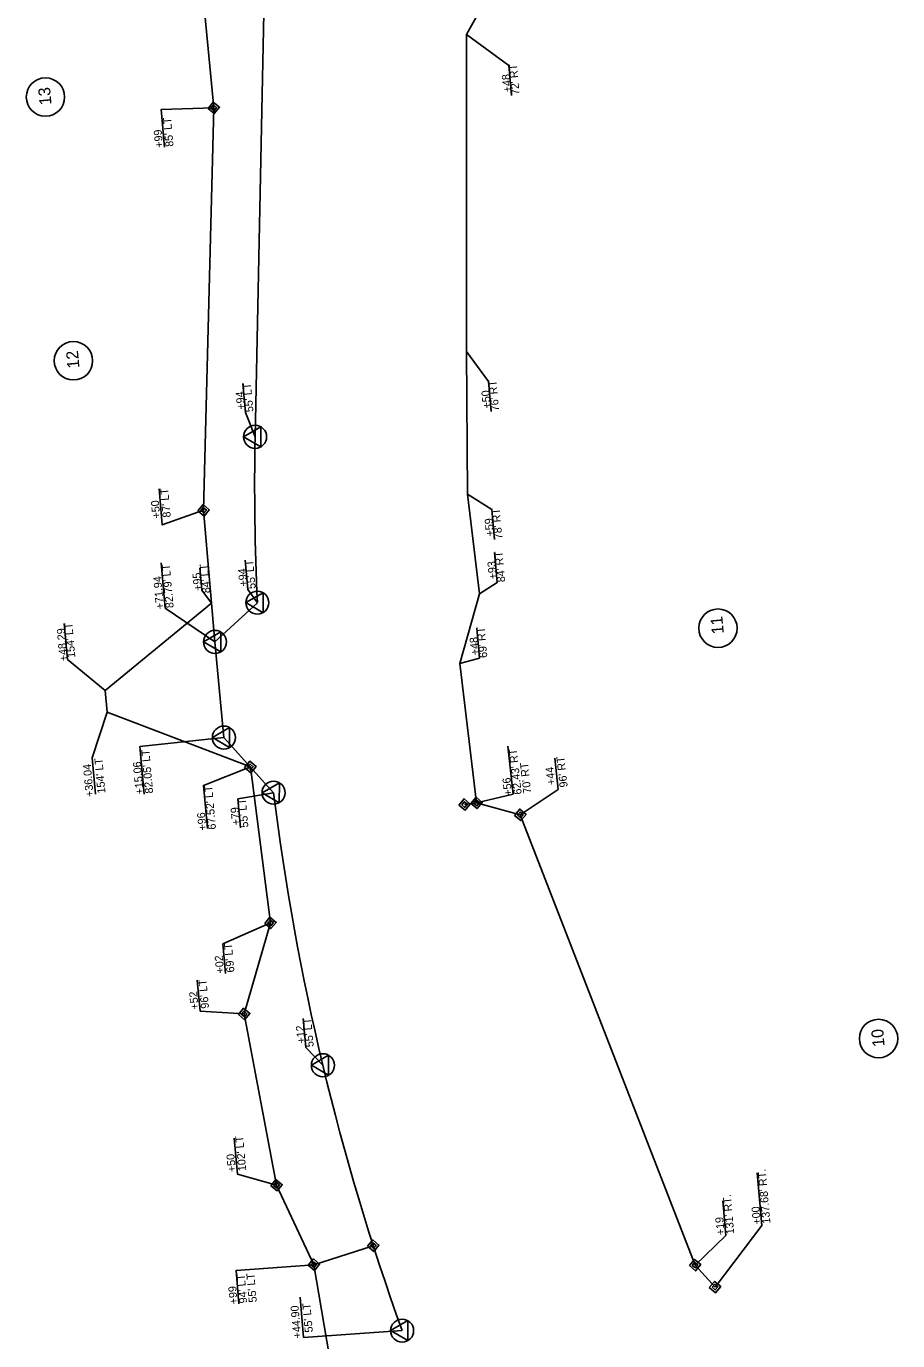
# Model space of a CAD drawing. Extents: x 1555582 to 1558054, y 687961 to 694065.
# Drawn here: x 1555953 to 1556498, y 690891 to 691713 of the extents above; entities that cross this region are included whole.
import ezdxf

# ---------------------------------------------------------------- set-up
doc = ezdxf.new("R2010")
doc.units = 0
for name, color, linetype in [('Exist Horizontal Alignment', 7, 'Continuous'), ('Exist Hydrographic FEMA Cross Section', 7, 'Continuous'), ('Exist Structure Major Bridge Seam', 7, 'Continuous'), ('Exist Structure Minor Drop Inlet Text', 7, 'Continuous'), ('Prop Approach Slab', 7, 'Continuous'), ('Prop Approach Slab Hatching', 7, 'Continuous'), ('Prop Boundary Easement Temporary Drainage Label', 7, 'Continuous'), ('Prop Drainage Structure Box Reinforced Concrete', 7, 'Continuous'), ('Prop Drainage Structure Catch Basin Grate 840 03F Label', 7, 'Continuous'), ('Prop Drainage Structure Catch Basin Grate 840 03G CELL', 7, 'Continuous'), ('Prop Drainage Structure Plot Symbol 50 Scale', 7, 'Continuous'), ('Prop Erosion Rip Rap Class II', 7, 'Continuous'), ('Prop Plan Preparation Excavation Hatching', 7, 'Continuous'), ('Scratch_Level_3', 7, 'Continuous')]:
    doc.layers.add(name, color=color, linetype=linetype)

msp = doc.modelspace()

# ---------------------------------------------------------------- linework, layer by layer
at = {"layer": 'Exist Horizontal Alignment'}
for p, q in [((1556088.15, 691489.59), (1556089.78, 691471.44)), ((1556089.56, 691379.07), (1556091.2, 691360.91)), ((1556023.7, 691262.72), (1556076.27, 691268.29)), ((1556023.7, 691262.72), (1556026.38, 691232.84)), ((1556084.98, 691229.93), (1556086.62, 691211.78)), ((1556125.85, 691092.78), (1556127.49, 691074.62)), ((1556123.88, 690918.49), (1556126.14, 690893.4)), ((1556126.14, 690893.4), (1556187.74, 690897.67))]:
    msp.add_line(p, q, dxfattribs=at)
for points in [[(1556089.78, 691471.44), (1556095.82, 691456.22)], [(1556036.97, 691377.54), (1556039.52, 691349.16), (1556070.71, 691328.04)], [(1556091.2, 691360.91), (1556097.21, 691352.58)], [(1556084.98, 691229.93), (1556107.34, 691233.83)], [(1556127.49, 691074.62), (1556138.16, 691063.56)]]:
    msp.add_lwpolyline(points, dxfattribs=at)
at = {"layer": 'Exist Hydrographic FEMA Cross Section'}
for p, q in [((1556095.82, 691456.22), (1556102.69, 691797.16)), ((1556070.71, 691328.04), (1556097.21, 691352.58)), ((1556076.27, 691268.29), (1556070.71, 691328.04)), ((1556107.34, 691233.83), (1556076.27, 691268.29))]:
    msp.add_line(p, q, dxfattribs=at)
for centre, radius, start, end in [((1557645.4, 691425.17), 1549.89, 178.85195, 182.68426), ((1557650.51, 691425.24), 1555, 187.07064, 199.83242)]:
    msp.add_arc(centre, radius, start, end, dxfattribs=at)
at = {"layer": 'Exist Structure Major Bridge Seam'}
for p, q in [((1556253.81, 691262.83), (1556257.14, 691233.01)), ((1556283.16, 691255.33), (1556285.35, 691235.76)), ((1556409.75, 690996.29), (1556412.71, 690963.43)), ((1556388.17, 690978.79), (1556390.13, 690957.04))]:
    msp.add_line(p, q, dxfattribs=at)
for points in [[(1556257.14, 691233.01), (1556234.25, 691227.48)], [(1556285.35, 691235.76), (1556261.6, 691219.95)], [(1556412.71, 690963.43), (1556383.4, 690924.9)], [(1556390.13, 690957.04), (1556370.92, 690938.61)]]:
    msp.add_lwpolyline(points, dxfattribs=at)
at = {"layer": 'Exist Structure Minor Drop Inlet Text'}
for p, q in [((1556254.53, 691688.34), (1556256.21, 691669.6)), ((1556241.73, 691490.73), (1556243.42, 691471.99)), ((1556243.77, 691410.76), (1556245.45, 691392.02)), ((1556245.53, 691383.89), (1556247.21, 691365.14)), ((1556061.33, 691374.32), (1556062.58, 691360.37)), ((1555976.47, 691339.66), (1555978.51, 691317)), ((1556234.37, 691336.57), (1556236.06, 691317.83)), ((1555978.51, 691317), (1556002.02, 691297.7)), ((1555993.99, 691255.63), (1555996.04, 691232.87))]:
    msp.add_line(p, q, dxfattribs=at)
for points in [[(1556254.53, 691688.34), (1556227.91, 691707.62)], [(1556241.73, 691490.73), (1556227.92, 691509.58)], [(1556243.77, 691410.76), (1556228.52, 691420.39)], [(1556247.21, 691365.14), (1556236.1, 691358.13)], [(1556062.58, 691360.37), (1556068.61, 691352.3)], [(1556236.06, 691317.83), (1556223.8, 691314.58)], [(1555993.99, 691255.63), (1556003.23, 691284.25)]]:
    msp.add_lwpolyline(points, dxfattribs=at)
at = {"layer": 'Prop Approach Slab'}
for p, q in [((1556069.96, 691661.8), (1556057.79, 691787.39)), ((1556063.58, 691410.31), (1556069.96, 691661.8)), ((1556070.71, 691328.04), (1556063.58, 691410.31)), ((1556105.41, 691152.46), (1556092.82, 691249.93)), ((1556088.94, 691095.54), (1556105.41, 691152.46)), ((1556109.18, 690988.56), (1556088.94, 691095.54)), ((1556132.53, 690938.86), (1556109.18, 690988.56)), ((1556169.67, 690950.76), (1556132.53, 690938.86))]:
    msp.add_line(p, q, dxfattribs=at)
at = {"layer": 'Prop Approach Slab Hatching'}
for p, q in [((1556069.96, 691661.8), (1556069.96, 691661.8)), ((1556063.58, 691410.31), (1556063.58, 691410.31)), ((1556092.82, 691249.93), (1556092.82, 691249.93)), ((1556226.75, 691226.43), (1556226.75, 691226.43)), ((1556234.25, 691227.48), (1556234.25, 691227.48)), ((1556261.6, 691219.95), (1556261.6, 691219.95)), ((1556105.41, 691152.46), (1556105.41, 691152.46)), ((1556088.94, 691095.54), (1556088.94, 691095.54)), ((1556109.18, 690988.56), (1556109.18, 690988.56)), ((1556169.67, 690950.76), (1556169.67, 690950.76)), ((1556132.53, 690938.86), (1556132.53, 690938.86)), ((1556370.92, 690938.61), (1556370.92, 690938.61)), ((1556383.4, 690924.9), (1556383.4, 690924.9))]:
    msp.add_line(p, q, dxfattribs=at)
at = {"layer": 'Prop Boundary Easement Temporary Drainage Label'}
for q in [(1556105.41, 691152.46), (1556077.22, 691120.77)]:
    msp.add_line((1556075.55, 691139.35), q, dxfattribs=at)
for points in [[(1556039.07, 691637.17), (1556036.96, 691660.67), (1556069.96, 691661.8)], [(1556035.71, 691423.65), (1556037.73, 691401.17), (1556063.58, 691410.31)], [(1556065.93, 691211.51), (1556063.51, 691238.41), (1556092.82, 691249.93)], [(1556059.63, 691116.77), (1556061.38, 691097.38), (1556088.94, 691095.54)], [(1556082.67, 691017.97), (1556084.7, 690995.47), (1556109.18, 690988.56)], [(1556085.73, 690914.49), (1556083.86, 690935.34), (1556132.53, 690938.86)]]:
    msp.add_lwpolyline(points, dxfattribs=at)
at = {"layer": 'Prop Drainage Structure Box Reinforced Concrete'}
for p, q in [((1556227.91, 691707.62), (1556245.55, 691739.27)), ((1556227.92, 691509.58), (1556227.91, 691707.62)), ((1556228.52, 691420.39), (1556227.92, 691509.58)), ((1556236.1, 691358.13), (1556228.52, 691420.39)), ((1556223.8, 691314.58), (1556236.1, 691358.13)), ((1556002.02, 691297.7), (1556068.61, 691352.3)), ((1556234.25, 691227.48), (1556223.8, 691314.58)), ((1556003.23, 691284.25), (1556002.02, 691297.7)), ((1556092.82, 691249.93), (1556003.23, 691284.25))]:
    msp.add_line(p, q, dxfattribs=at)
at = {"layer": 'Prop Drainage Structure Catch Basin Grate 840 03F Label'}
for p, q in [((1555964.72, 691668.55), (1555964.72, 691668.55)), ((1555982.21, 691503.75), (1555982.21, 691503.75)), ((1556385.21, 691336.63), (1556385.21, 691336.63)), ((1556485.62, 691080.21), (1556485.62, 691080.21))]:
    msp.add_line(p, q, dxfattribs=at)
for centre in [(1555964.72, 691668.55), (1555982.21, 691503.75), (1556385.21, 691336.63), (1556485.62, 691080.21)]:
    msp.add_circle(centre, 12, dxfattribs=at)
at = {"layer": 'Prop Drainage Structure Plot Symbol 50 Scale'}
for p, q in [((1556095.82, 691456.22), (1556095.82, 691456.22)), ((1556097.21, 691352.58), (1556097.21, 691352.58)), ((1556070.71, 691328.04), (1556070.71, 691328.04)), ((1556076.27, 691268.29), (1556076.27, 691268.29)), ((1556107.34, 691233.83), (1556107.34, 691233.83)), ((1556138.17, 691063.51), (1556138.17, 691063.51)), ((1556187.74, 690897.67), (1556187.74, 690897.67))]:
    msp.add_line(p, q, dxfattribs=at)
for points in [[(1556099.41, 691449.97), (1556088.62, 691456.23), (1556099.43, 691462.47)], [(1556100.8, 691346.33), (1556090.01, 691352.59), (1556100.82, 691358.83)], [(1556074.3, 691321.79), (1556063.51, 691328.05), (1556074.32, 691334.29)], [(1556079.86, 691262.04), (1556069.07, 691268.3), (1556079.88, 691274.54)], [(1556110.93, 691227.57), (1556100.14, 691233.84), (1556110.95, 691240.07)], [(1556141.76, 691057.25), (1556130.97, 691063.52), (1556141.78, 691069.75)], [(1556191.33, 690891.42), (1556180.54, 690897.68), (1556191.35, 690903.92)]]:
    msp.add_lwpolyline(points, close=True, dxfattribs=at)
for centre in [(1556095.82, 691456.22), (1556097.21, 691352.58), (1556070.71, 691328.04), (1556076.27, 691268.29), (1556107.34, 691233.83), (1556138.17, 691063.51), (1556187.74, 690897.67)]:
    msp.add_circle(centre, 7.2, dxfattribs=at)
at = {"layer": 'Prop Erosion Rip Rap Class II'}
for p, q in [((1556226.75, 691226.43), (1556234.25, 691227.48)), ((1556261.6, 691219.95), (1556234.25, 691227.48)), ((1556370.92, 690938.61), (1556261.6, 691219.95)), ((1556383.4, 690924.9), (1556370.92, 690938.61))]:
    msp.add_line(p, q, dxfattribs=at)
at = {"layer": 'Prop Plan Preparation Excavation Hatching'}
msp.add_line((1556165.07, 690748.64), (1556132.53, 690938.86), dxfattribs=at)
at = {"layer": 'Scratch_Level_3'}
for points in [[(1556066.37, 691661.47), (1556069.64, 691665.38), (1556073.54, 691662.12), (1556070.28, 691658.21)], [(1556068.17, 691661.64), (1556069.8, 691663.59), (1556071.75, 691661.96), (1556070.12, 691660)], [(1556060, 691409.99), (1556063.26, 691413.9), (1556067.17, 691410.63), (1556063.91, 691406.72)], [(1556061.79, 691410.15), (1556063.42, 691412.1), (1556065.38, 691410.47), (1556063.74, 691408.52)], [(1556089.24, 691249.61), (1556092.5, 691253.51), (1556096.41, 691250.25), (1556093.15, 691246.34)], [(1556091.03, 691249.77), (1556092.66, 691251.72), (1556094.62, 691250.09), (1556092.99, 691248.14)], [(1556223.17, 691226.11), (1556226.43, 691230.01), (1556230.34, 691226.75), (1556227.07, 691222.84)], [(1556224.96, 691226.27), (1556226.59, 691228.22), (1556228.54, 691226.59), (1556226.91, 691224.64)], [(1556230.67, 691227.15), (1556233.93, 691231.06), (1556237.84, 691227.8), (1556234.58, 691223.89)], [(1556232.46, 691227.31), (1556234.09, 691229.27), (1556236.05, 691227.64), (1556234.41, 691225.68)], [(1556258.02, 691219.63), (1556261.28, 691223.54), (1556265.19, 691220.28), (1556261.92, 691216.37)], [(1556259.81, 691219.79), (1556261.44, 691221.75), (1556263.39, 691220.11), (1556261.76, 691218.16)], [(1556101.82, 691152.14), (1556105.08, 691156.05), (1556108.99, 691152.79), (1556105.73, 691148.88)], [(1556103.61, 691152.3), (1556105.24, 691154.26), (1556107.2, 691152.63), (1556105.57, 691150.67)], [(1556085.35, 691095.22), (1556088.61, 691099.13), (1556092.52, 691095.87), (1556089.26, 691091.96)], [(1556087.14, 691095.38), (1556088.78, 691097.34), (1556090.73, 691095.7), (1556089.1, 691093.75)], [(1556105.59, 690988.24), (1556108.85, 690992.15), (1556112.76, 690988.89), (1556109.5, 690984.98)], [(1556107.38, 690988.4), (1556109.01, 690990.36), (1556110.97, 690988.73), (1556109.34, 690986.77)], [(1556166.08, 690950.44), (1556169.35, 690954.35), (1556173.25, 690951.09), (1556169.99, 690947.18)], [(1556167.88, 690950.6), (1556169.51, 690952.56), (1556171.46, 690950.92), (1556169.83, 690948.97)], [(1556128.94, 690938.54), (1556132.21, 690942.45), (1556136.11, 690939.19), (1556132.85, 690935.28)], [(1556130.74, 690938.7), (1556132.37, 690940.66), (1556134.32, 690939.02), (1556132.69, 690937.07)], [(1556367.33, 690938.29), (1556370.6, 690942.2), (1556374.5, 690938.93), (1556371.24, 690935.03)], [(1556369.13, 690938.45), (1556370.76, 690940.4), (1556372.71, 690938.77), (1556371.08, 690936.82)], [(1556379.81, 690924.57), (1556383.08, 690928.48), (1556386.98, 690925.22), (1556383.72, 690921.31)], [(1556381.61, 690924.74), (1556383.24, 690926.69), (1556385.19, 690925.06), (1556383.56, 690923.1)]]:
    msp.add_lwpolyline(points, close=True, dxfattribs=at)

# ---------------------------------------------------------------- texts
at = {"layer": 'Exist Horizontal Alignment'}
for s, p in [("55' LT", (1556094.79, 691471.87)), ('+94', (1556089.57, 691473.45)), ("82.79' LT", (1556044.9, 691349.4)), ('+94', (1556090.99, 691362.93)), ("55' LT", (1556096.2, 691361.34)), ('+71.94', (1556038.85, 691348.74)), ("82.05' LT", (1556032.09, 691233.54)), ('+15.06', (1556026.11, 691233)), ("55' LT", (1556091.62, 691212.2)), ('+79', (1556086.42, 691213.69)), ('+12', (1556127.21, 691077.37)), ("55' LT", (1556132.49, 691075.05)), ('+44.90', (1556124.73, 690893.03)), ("55' LT", (1556131.93, 690896.73))]:
    msp.add_text(s, height=5, rotation=95.14143, dxfattribs=at).set_placement(p)
at = {"layer": 'Exist Structure Major Bridge Seam'}
for s, rotation, p in [("62.43' RT", 96.3743, (1556262.56, 691232.91)), ("70' RT", 96.3743, (1556268.52, 691233.57)), ('+44', 96.3743, (1556283.55, 691238.9)), ("96' RT", 96.3743, (1556291.27, 691237.4)), ('+56', 96.3743, (1556256.59, 691232.24)), ("137.68' RT.", 95.14143, (1556418.07, 690964.74)), ("131' RT.", 95.14143, (1556395.41, 690958.13)), ('+00', 95.14143, (1556412.1, 690964.2)), ('+19', 95.14143, (1556389.43, 690957.59))]:
    msp.add_text(s, height=5, rotation=rotation, dxfattribs=at).set_placement(p)
at = {"layer": 'Exist Structure Minor Drop Inlet Text'}
for s, p in [("72' RT", (1556261.22, 691670.02)), ('+48', (1556255.99, 691671.77)), ("76' RT", (1556248.43, 691472.41)), ('+50', (1556243.2, 691474.16)), ("78' RT", (1556250.46, 691392.45)), ('+59', (1556245.23, 691394.23)), ("84' RT", (1556252.22, 691365.57)), ("84' LT", (1556067.78, 691358.69)), ('+93', (1556246.98, 691367.42)), ('+95', (1556062.57, 691360.24)), ("154' LT", (1555983.44, 691318.3)), ('+48.29', (1555978.55, 691316.24)), ("69' RT", (1556241.06, 691318.26)), ('+48', (1556235.84, 691320.01)), ('+36.04', (1555994.91, 691231.42)), ("154' LT", (1556002.25, 691233.6))]:
    msp.add_text(s, height=5, rotation=95.14143, dxfattribs=at).set_placement(p)
at = {"layer": 'Prop Boundary Easement Temporary Drainage Label'}
for s, p in [("85' LT", (1556044.8, 691637.69)), ('+99', (1556038.32, 691637.11)), ("87' LT", (1556043.07, 691406.01)), ('+50', (1556036.59, 691405.43)), ("67.52' LT", (1556071.39, 691210.96)), ('+96', (1556065.41, 691210.43)), ("69' LT", (1556082.91, 691121.71)), ('+02', (1556076.44, 691121.12)), ("96' LT", (1556066.99, 691099.13)), ('+52', (1556060.52, 691098.55)), ("102' LT", (1556090.28, 690997.59)), ('+50', (1556083.81, 690997)), ("94' LT", (1556090.92, 690914.96)), ("55' LT", (1556096.9, 690915.5)), ('+99', (1556084.94, 690914.42))]:
    msp.add_text(s, height=5, rotation=95.14143, dxfattribs=at).set_placement(p)
at = {"layer": 'Prop Drainage Structure Catch Basin Grate 840 03G CELL'}
for s, p in [('13', (1555968.54, 691663.87)), ('12', (1555986, 691499.31)), ('11', (1556388.91, 691333.26)), ('10', (1556489.45, 691075.37))]:
    msp.add_text(s, height=7.5, rotation=95.14143, dxfattribs=at).set_placement(p)

doc.saveas('drawing.dxf')
